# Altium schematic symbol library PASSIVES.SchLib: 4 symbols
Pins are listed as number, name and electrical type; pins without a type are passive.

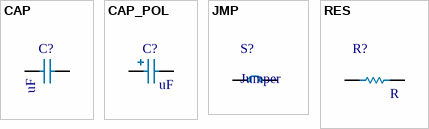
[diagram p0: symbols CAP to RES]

## CAP
designator C?, comment value uF  (hidden comment: Capacitor)
Capacitor Non Polarized
footprint CGA5L2 (TDK CGA5L TDK Ceramic Capacitor)
footprint C0603 (Kemet C0603 Ceramic Capacitor)
pins: 1, 2
1 alternate drawing of the same symbol

## CAP_POL
designator C?, comment value uF  (hidden comment: Polarized Capacitor)
Polarized Capacitor - Tantalum
footprint TCAXM8R (TCA Tantalum Capacitor 1206 Rohm)
footprint TCFGBXM8R (Rohm TCFGB Series Tantalum Capacitor)
pins: 1, 2
1 alternate drawing of the same symbol

## JMP
designator S?, comment Jumper
footprint JUMPER (Jumper)
pins: 1, 2

## RES
designator R?, comment value R  (hidden comment: Resistor)
footprint ERA3A (ERA3A Panasonic Thin Film Resistor 0603)
footprint ERA6A (ERA6A Panasonic Thin Film Resistor 0805)
pins: 1, 2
